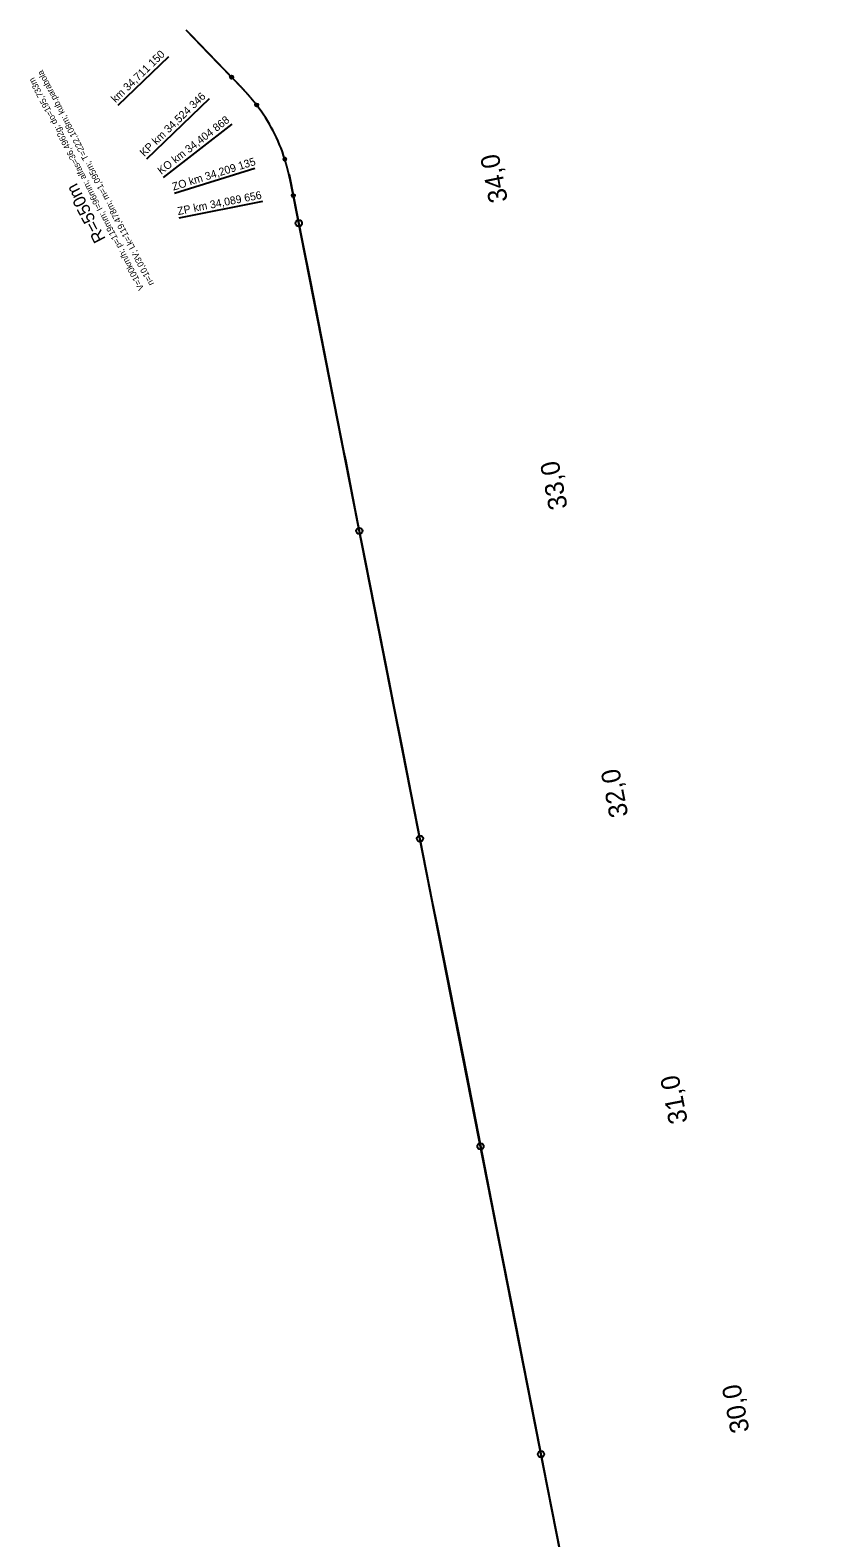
# Model space of a CAD drawing. Extents: x -504999 to -493096, y -1330712 to -1305226.
# Drawn here: x -496237 to -493746, y -1310033 to -1305226 of the extents above; entities that cross this region are included whole.
import ezdxf

# ---------------------------------------------------------------- set-up
doc = ezdxf.new("R2010")
doc.units = 0
for name, color, linetype in [('0_HM', 7, 'Continuous'), ('0_obluky', 7, 'Continuous'), ('0_popis oblukov', 7, 'Continuous'), ('0_stanicenie oblukov', 7, 'Continuous'), ('dotyčnice', 7, 'Continuous'), ('Level 1', 7, 'Continuous')]:
    doc.layers.add(name, color=color, linetype=linetype)

msp = doc.modelspace()

# ---------------------------------------------------------------- linework, layer by layer
at = {"layer": '0_HM'}
for centre in [(-495379.9, -1305841.2), (-495186.6, -1306822.3), (-494993.3, -1307803.5), (-494800, -1308784.6), (-494606.7, -1309765.8)]:
    msp.add_circle(centre, 10, dxfattribs=at)
at = {"layer": '0_obluky'}
for p, q in [((-495594.4, -1305375.5), (-495738.9, -1305225.8)), ((-495796.1, -1305310.6), (-495957.3, -1305466.2)), ((-493745.9, -1314135.5), (-495397.2, -1305753.2))]:
    msp.add_line(p, q, dxfattribs=at)
for points in [[(-495594.4, -1305375.5), (-495593.7, -1305376.2), (-495593, -1305377), (-495592.3, -1305377.7), (-495591.6, -1305378.4), (-495590.9, -1305379.1), (-495590.2, -1305379.8), (-495589.5, -1305380.6), (-495588.8, -1305381.3), (-495588.1, -1305382), (-495587.4, -1305382.7), (-495586.8, -1305383.5), (-495586.1, -1305384.2), (-495585.4, -1305384.9), (-495584.7, -1305385.6), (-495584, -1305386.3), (-495583.3, -1305387.1), (-495582.6, -1305387.8), (-495581.9, -1305388.5), (-495581.2, -1305389.2), (-495580.5, -1305390), (-495579.8, -1305390.7), (-495579.1, -1305391.4), (-495578.4, -1305392.1), (-495577.7, -1305392.9), (-495577, -1305393.6), (-495576.3, -1305394.3), (-495575.6, -1305395), (-495574.9, -1305395.8), (-495574.3, -1305396.5), (-495573.6, -1305397.2), (-495572.9, -1305397.9), (-495572.2, -1305398.7), (-495571.5, -1305399.4), (-495570.8, -1305400.1), (-495570.1, -1305400.8), (-495569.4, -1305401.6), (-495568.7, -1305402.3), (-495568, -1305403), (-495567.4, -1305403.8), (-495566.7, -1305404.5), (-495566, -1305405.2), (-495565.3, -1305405.9), (-495564.6, -1305406.7), (-495563.9, -1305407.4), (-495563.2, -1305408.1), (-495562.6, -1305408.9), (-495561.9, -1305409.6), (-495561.2, -1305410.3), (-495560.5, -1305411.1), (-495559.8, -1305411.8), (-495559.1, -1305412.5), (-495558.5, -1305413.3), (-495557.8, -1305414), (-495557.1, -1305414.8), (-495556.4, -1305415.5), (-495555.7, -1305416.2), (-495555.1, -1305417), (-495554.4, -1305417.7), (-495553.7, -1305418.4), (-495553, -1305419.2), (-495552.3, -1305419.9), (-495551.7, -1305420.7), (-495551, -1305421.4), (-495550.3, -1305422.2), (-495549.6, -1305422.9), (-495549, -1305423.6), (-495548.3, -1305424.4), (-495547.6, -1305425.1), (-495547, -1305425.9), (-495546.3, -1305426.6), (-495545.6, -1305427.4), (-495545, -1305428.1), (-495544.3, -1305428.9), (-495543.6, -1305429.6), (-495543, -1305430.4), (-495542.3, -1305431.1), (-495541.6, -1305431.9), (-495541, -1305432.6), (-495540.3, -1305433.4), (-495539.6, -1305434.1), (-495539, -1305434.9), (-495538.3, -1305435.7), (-495537.7, -1305436.4), (-495537, -1305437.2), (-495536.3, -1305437.9), (-495535.7, -1305438.7), (-495535, -1305439.5), (-495534.4, -1305440.2), (-495533.7, -1305441), (-495533.1, -1305441.7), (-495532.4, -1305442.5), (-495531.8, -1305443.3), (-495531.1, -1305444), (-495530.5, -1305444.8), (-495529.8, -1305445.6), (-495529.2, -1305446.4), (-495528.5, -1305447.1), (-495527.9, -1305447.9), (-495527.3, -1305448.7), (-495526.6, -1305449.4), (-495526, -1305450.2), (-495525.3, -1305451), (-495524.7, -1305451.8), (-495524.1, -1305452.6), (-495523.4, -1305453.3), (-495522.8, -1305454.1), (-495522.2, -1305454.9), (-495521.5, -1305455.7), (-495520.9, -1305456.5), (-495520.3, -1305457.3), (-495519.6, -1305458), (-495519, -1305458.8), (-495518.4, -1305459.6), (-495517.8, -1305460.4), (-495517.1, -1305461.2), (-495516.5, -1305462), (-495515.9, -1305462.8), (-495515.3, -1305463.6), (-495514.6, -1305464.4)], [(-495397.2, -1305753.2), (-495397.4, -1305752.2), (-495397.6, -1305751.3), (-495397.8, -1305750.3), (-495398, -1305749.3), (-495398.2, -1305748.3), (-495398.4, -1305747.3), (-495398.6, -1305746.3), (-495398.8, -1305745.4), (-495399, -1305744.4), (-495399.2, -1305743.4), (-495399.3, -1305742.4), (-495399.5, -1305741.4), (-495399.7, -1305740.4), (-495399.9, -1305739.5), (-495400.1, -1305738.5), (-495400.3, -1305737.5), (-495400.5, -1305736.5), (-495400.7, -1305735.5), (-495400.9, -1305734.5), (-495401.1, -1305733.6), (-495401.3, -1305732.6), (-495401.5, -1305731.6), (-495401.7, -1305730.6), (-495401.9, -1305729.6), (-495402.1, -1305728.6), (-495402.3, -1305727.7), (-495402.5, -1305726.7), (-495402.7, -1305725.7), (-495402.9, -1305724.7), (-495403.1, -1305723.7), (-495403.3, -1305722.7), (-495403.5, -1305721.8), (-495403.7, -1305720.8), (-495403.9, -1305719.8), (-495404.1, -1305718.8), (-495404.3, -1305717.8), (-495404.5, -1305716.8), (-495404.7, -1305715.9), (-495404.9, -1305714.9), (-495405.1, -1305713.9), (-495405.3, -1305712.9), (-495405.5, -1305711.9), (-495405.7, -1305711), (-495406, -1305710), (-495406.2, -1305709), (-495406.4, -1305708), (-495406.6, -1305707), (-495406.8, -1305706.1), (-495407, -1305705.1), (-495407.2, -1305704.1), (-495407.4, -1305703.1), (-495407.6, -1305702.1), (-495407.9, -1305701.2), (-495408.1, -1305700.2), (-495408.3, -1305699.2), (-495408.5, -1305698.2), (-495408.7, -1305697.2), (-495408.9, -1305696.3), (-495409.2, -1305695.3), (-495409.4, -1305694.3), (-495409.6, -1305693.3), (-495409.8, -1305692.3), (-495410.1, -1305691.4), (-495410.3, -1305690.4), (-495410.5, -1305689.4), (-495410.7, -1305688.4), (-495411, -1305687.5), (-495411.2, -1305686.5), (-495411.4, -1305685.5), (-495411.6, -1305684.5), (-495411.9, -1305683.5), (-495412.1, -1305682.6), (-495412.3, -1305681.6), (-495412.6, -1305680.6), (-495412.8, -1305679.6), (-495413.1, -1305678.7), (-495413.3, -1305677.7), (-495413.5, -1305676.7), (-495413.8, -1305675.7), (-495414, -1305674.8), (-495414.3, -1305673.8), (-495414.5, -1305672.8), (-495414.7, -1305671.8), (-495415, -1305670.9), (-495415.2, -1305669.9), (-495415.5, -1305668.9), (-495415.7, -1305668), (-495416, -1305667), (-495416.2, -1305666), (-495416.5, -1305665), (-495416.8, -1305664.1), (-495417, -1305663.1), (-495417.3, -1305662.1), (-495417.5, -1305661.2), (-495417.8, -1305660.2), (-495418.1, -1305659.2), (-495418.3, -1305658.2), (-495418.6, -1305657.3), (-495418.9, -1305656.3), (-495419.1, -1305655.3), (-495419.4, -1305654.4), (-495419.7, -1305653.4), (-495419.9, -1305652.4), (-495420.2, -1305651.5), (-495420.5, -1305650.5), (-495420.8, -1305649.5), (-495421.1, -1305648.6), (-495421.3, -1305647.6), (-495421.6, -1305646.6), (-495421.9, -1305645.7), (-495422.2, -1305644.7), (-495422.5, -1305643.7), (-495422.8, -1305642.8), (-495423.1, -1305641.8), (-495423.3, -1305640.8), (-495423.6, -1305639.9), (-495423.9, -1305638.9), (-495424.2, -1305637.9), (-495424.5, -1305637)]]:
    msp.add_lwpolyline(points, dxfattribs=at)
for centre in [(-495594.4, -1305375.5), (-495514.6, -1305464.4), (-495424.5, -1305637), (-495397.2, -1305753.2)]:
    msp.add_circle(centre, 5, dxfattribs=at)
msp.add_arc((-495949.4, -1305801.2), 550, 17.373, 37.7633, dxfattribs=at)
at = {"layer": '0_stanicenie oblukov'}
for p, q in [((-495666.4, -1305445), (-495865.9, -1305637.6)), ((-495593.7, -1305525.6), (-495812.7, -1305695.3)), ((-495520, -1305666.8), (-495776.6, -1305747.1)), ((-495495.3, -1305772.6), (-495762.9, -1305825.3))]:
    msp.add_line(p, q, dxfattribs=at)
at = {"layer": 'dotyčnice'}
for p, q in [((-495559.4, -1305411.8), (-495724.2, -1305241.1)), ((-493763.1, -1314048), (-495410.5, -1305685.7))]:
    msp.add_line(p, q, dxfattribs=at)
at = {"layer": 'Level 1'}
msp.add_line((-494973.3, -1307907.2), (-494955.1, -1307999.7), dxfattribs=at)
for points in [[(-495738.9, -1305225.8), (-495667.5, -1305300), (-495559.4, -1305411.8)], [(-495410.5, -1305685.7), (-495367.7, -1305901.7), (-495343, -1306028.6), (-495265.9, -1306420.2), (-495237.1, -1306566.6)], [(-495237.1, -1306566.6), (-495230.2, -1306599.8), (-495228.1, -1306611.9), (-495195.3, -1306779.3), (-495169.2, -1306911.5), (-495093, -1307299.6), (-495076.7, -1307381.9), (-495051.4, -1307508.9), (-495022.3, -1307656.9), (-494973.3, -1307907.2)], [(-494955.1, -1307999.7), (-494937.3, -1308087.2), (-494908.5, -1308230.7), (-494873.5, -1308406.6), (-494844.1, -1308557.6)], [(-494844.1, -1308557.6), (-494750.9, -1309033.2), (-494685.7, -1309366.1), (-494664.1, -1309477.1), (-494628, -1309660.7), (-494589.7, -1309856.8), (-494541.4, -1310099.8), (-494450.6, -1310562.1), (-494398.7, -1310826.3), (-494346.7, -1311085.2), (-494265.3, -1311500.4)]]:
    msp.add_lwpolyline(points, dxfattribs=at)

# ---------------------------------------------------------------- texts
at = {"layer": '0_HM'}
for s, p in [('34,0', (-494712.6, -1305769.9)), ('33,0', (-494521.6, -1306748.5)), ('32,0', (-494328, -1307729.9)), ('31,0', (-494138.4, -1308706.8)), ('30,0', (-493941.5, -1309692.2))]:
    msp.add_text(s, height=60, rotation=101.1449, dxfattribs=at).set_placement(p)
at = {"layer": '0_obluky'}
msp.add_text('km 34,711 150', height=25, rotation=43.9915, dxfattribs=at).set_placement((-495964.3, -1305459))
at = {"layer": '0_popis oblukov'}
for s, height, p in [('n=10,03V; Lk=119,478m; m=1,095m; T=222,108m; kub.parabola', 20, (-495841.4, -1306034.1)), ('V=100km/h; p=119mm; I=96mm; alfas=36,4962g; do=195,733m', 20, (-495873.1, -1306049)), ('R=550m', 40, (-495995, -1305891.2))]:
    msp.add_text(s, height=height, rotation=117.5681, dxfattribs=at).set_placement(p)
at = {"layer": '0_stanicenie oblukov'}
for s, rotation, p in [('KP km 34,524 346', 43.9915, (-495872.8, -1305630.4)), ('KO km 34,404 868', 37.7633, (-495818.8, -1305687.4)), ('ZO km 34,209 135', 17.373, (-495779.6, -1305737.6)), ('ZP km 34,089 656', 11.1449, (-495764.8, -1305815.5))]:
    msp.add_text(s, height=25, rotation=rotation, dxfattribs=at).set_placement(p)

doc.saveas('drawing.dxf')
